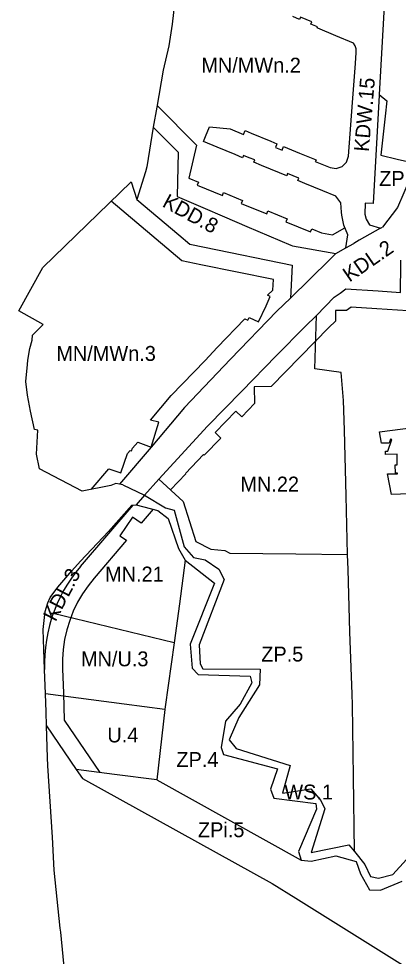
# Model space of a CAD drawing. Extents: x 7419601 to 7420547, y 5548907 to 5549873.
# Drawn here: x 7419651.8 to 7419779.2, y 5549211.8 to 5549526.6 of the extents above; entities that cross this region are included whole.
import ezdxf

# ---------------------------------------------------------------- set-up
doc = ezdxf.new("R2010")
doc.units = 0
for name, color, linetype in [('LIN_linie_rozgraniczajace', 7, 'Continuous'), ('LIN_nieprzekraczalna linia zabudowy', 7, 'Continuous'), ('TXT_opisy_przeznaczen', 7, 'Continuous')]:
    doc.layers.add(name, color=color, linetype=linetype)

msp = doc.modelspace()

# ---------------------------------------------------------------- linework, layer by layer
at = {"layer": 'LIN_linie_rozgraniczajace'}
for p, q in [((7419773.28, 5549456.31), (7419766.1, 5549452.22)), ((7419766.1, 5549452.22), (7419764.28, 5549451.17)), ((7419761.67, 5549449.69), (7419764.28, 5549451.17)), ((7419742.99, 5549432.82), (7419756.11, 5549445.62)), ((7419686.77, 5549370.13), (7419694.08, 5549366.64)), ((7419698.87, 5549371.96), (7419694.08, 5549366.64)), ((7419694.08, 5549366.64), (7419691.23, 5549363.38)), ((7419672.54, 5549342.67), (7419690.24, 5549363.28)), ((7419703.96, 5549317.03), (7419663.4, 5549326.89)), ((7419698.21, 5549271.06), (7419746.57, 5549244.06))]:
    msp.add_line(p, q, dxfattribs=at)
for points in [[(7419777.91, 5549592.55), (7419774.39, 5549528.85), (7419772.86, 5549501.2), (7419772.85, 5549500.98)], [(7419707.9, 5549572.09), (7419706.24, 5549550.17), (7419705.93, 5549547.4), (7419703.37, 5549524.79), (7419702.15, 5549517.49), (7419700.32, 5549509.31), (7419698.15, 5549496.9), (7419696.97, 5549490.2)], [(7419761.67, 5549449.69), (7419762.32, 5549454.07), (7419760.99, 5549457.25), (7419760.64, 5549458.99), (7419760.29, 5549460.68), (7419760.22, 5549461.67), (7419759.98, 5549464.76), (7419758.29, 5549467.03), (7419753.93, 5549468.82), (7419750.91, 5549470.07), (7419747.88, 5549471.32), (7419745.53, 5549472.29), (7419745.86, 5549473.07), (7419743.91, 5549473.87), (7419742.09, 5549474.62), (7419741.78, 5549473.84), (7419739.3, 5549474.86), (7419736.29, 5549476.1), (7419733.26, 5549477.34), (7419730.74, 5549478.38), (7419731.06, 5549479.17), (7419729.19, 5549479.94), (7419727.31, 5549480.71), (7419726.98, 5549479.93), (7419724.5, 5549480.97), (7419721.49, 5549482.23), (7419718.45, 5549483.48), (7419713.85, 5549485.36), (7419714.54, 5549487.03), (7419715.88, 5549490.27), (7419722.8, 5549489.61), (7419727.25, 5549487.77), (7419727.77, 5549489.02), (7419729.89, 5549488.14), (7419736.42, 5549485.45), (7419738.48, 5549484.6), (7419737.97, 5549483.36), (7419739.08, 5549482.89), (7419740.19, 5549482.44), (7419740.7, 5549483.69), (7419746.1, 5549481.46), (7419749.37, 5549480.12), (7419751.62, 5549479.19), (7419751.38, 5549478.64), (7419756.31, 5549476.61), (7419758.38, 5549476.28), (7419760.39, 5549476.93), (7419761.87, 5549478.42), (7419762.5, 5549480.43), (7419763.87, 5549498.44), (7419764.85, 5549511.52), (7419765.12, 5549515.25), (7419765.06, 5549516.49), (7419764.75, 5549517.47), (7419764.24, 5549518.36), (7419758.29, 5549520.87), (7419752.26, 5549523.43), (7419752.02, 5549523.54), (7419752.15, 5549523.87), (7419749.89, 5549524.8), (7419750.2, 5549525.59), (7419748.34, 5549526.35), (7419746.44, 5549527.14), (7419746.11, 5549526.35), (7419743.85, 5549527.29)], [(7419772.85, 5549500.98), (7419770.83, 5549464.52), (7419768.15, 5549464.7), (7419768.03, 5549461.02), (7419768.4, 5549459.24), (7419769.53, 5549457.42), (7419773.28, 5549456.31), (7419773.89, 5549456.66)], [(7419772.86, 5549501.2), (7419775.41, 5549499), (7419774.83, 5549493.83), (7419773.35, 5549480.78), (7419778.88, 5549479.48), (7419785.33, 5549477.97)], [(7419696.97, 5549490.2), (7419694.84, 5549476.85), (7419694.33, 5549475.22)], [(7419696.97, 5549490.2), (7419705.37, 5549481.74), (7419705.01, 5549466.93), (7419713.61, 5549463.23), (7419720.93, 5549460.09), (7419728.41, 5549456.87), (7419735.8, 5549453.71), (7419743.11, 5549450.55), (7419743.67, 5549450.31), (7419758.27, 5549447.73)], [(7419785.45, 5549478.26), (7419785.33, 5549477.97), (7419779.01, 5549463.24), (7419773.89, 5549456.66)], [(7419694.33, 5549475.22), (7419691.42, 5549465.86)], [(7419686.77, 5549370.13), (7419685.59, 5549370.35), (7419684.41, 5549370.57), (7419682.74, 5549369.89), (7419673.14, 5549367.93), (7419658.79, 5549375.45), (7419657.77, 5549380.42), (7419658.24, 5549388.47), (7419657.12, 5549388.69), (7419655.81, 5549394.88), (7419654.71, 5549400.19), (7419654.17, 5549404.81), (7419654.71, 5549410.47), (7419654.85, 5549411.95), (7419655.5, 5549415.92), (7419656.29, 5549418.71), (7419656.41, 5549420.32), (7419660.01, 5549423.96), (7419651.81, 5549428.47), (7419659.89, 5549443.1), (7419689.55, 5549471.82), (7419691.42, 5549465.86)], [(7419691.42, 5549465.86), (7419698.5, 5549459.94), (7419705.59, 5549454.01), (7419709.25, 5549450.87), (7419714.16, 5549449.88), (7419743.61, 5549443.9), (7419742.99, 5549432.82)], [(7419756.11, 5549445.62), (7419758.27, 5549447.73), (7419758.31, 5549447.77), (7419761.67, 5549449.69)], [(7419751.74, 5549427), (7419757.74, 5549433.05), (7419759.68, 5549434.46), (7419761.59, 5549435.87), (7419772.43, 5549435.18), (7419779.99, 5549434.69), (7419780.12, 5549444.2), (7419780.14, 5549445.53)], [(7419742.99, 5549432.82), (7419738.43, 5549428.39), (7419722.95, 5549412.24), (7419707.46, 5549396.1), (7419696.31, 5549382.76), (7419685.59, 5549370.35)], [(7419751.74, 5549427), (7419747.99, 5549423.22), (7419738.24, 5549413.4), (7419726.7, 5549401.57), (7419715.17, 5549389.75), (7419698.87, 5549371.96)], [(7419762.23, 5549346.67), (7419761.71, 5549366.37), (7419761.12, 5549388.42), (7419760.86, 5549398.45), (7419760.08, 5549407.83), (7419751.2, 5549408.99), (7419751.74, 5549427)], [(7419698.87, 5549371.96), (7419706.96, 5549364.5), (7419711.27, 5549351.1), (7419716.32, 5549348.47), (7419720.98, 5549348.02), (7419722.66, 5549347.17), (7419744.84, 5549346.89), (7419762.23, 5549346.67)], [(7419694.08, 5549366.64), (7419701.12, 5549362.38), (7419704.03, 5549361.57), (7419707.33, 5549349.23), (7419710.51, 5549345.74), (7419714.4, 5549344.92), (7419719.02, 5549341.8), (7419720.82, 5549338.28), (7419712.42, 5549316.32), (7419712.72, 5549310.01), (7419713.64, 5549308.26), (7419732.89, 5549308.23), (7419732.62, 5549302.94), (7419725.69, 5549292.02), (7419722.45, 5549284.49), (7419724.81, 5549281.56), (7419742.94, 5549275.84), (7419740.33, 5549266.59), (7419749.87, 5549267.98), (7419753.2, 5549264.14), (7419754.55, 5549261.27), (7419749.99, 5549246.63), (7419762.65, 5549249.26), (7419764.51, 5549246.94)], [(7419660.84, 5549299.92), (7419660.51, 5549308.1), (7419659.98, 5549321.47), (7419660.69, 5549327.55), (7419661.62, 5549330.48), (7419662.39, 5549332.24), (7419664.89, 5549335.74), (7419669.61, 5549341.18), (7419672.51, 5549344.47), (7419681.9, 5549354.46), (7419689.78, 5549363.23), (7419690.24, 5549363.28), (7419691.23, 5549363.38)], [(7419691.23, 5549363.38), (7419698.55, 5549361.52), (7419702.02, 5549358.75), (7419705.41, 5549348.71), (7419707.66, 5549344.84)], [(7419707.66, 5549344.84), (7419705.78, 5549330.1), (7419703.96, 5549317.03), (7419701, 5549295.54), (7419700.88, 5549294.65)], [(7419707.66, 5549344.84), (7419717.51, 5549337.05), (7419709.37, 5549316.61), (7419709.99, 5549308.52), (7419712.02, 5549306.36), (7419729.47, 5549305.82), (7419730.07, 5549303.6), (7419726.12, 5549296.43), (7419721.2, 5549290.75), (7419719.76, 5549281.9), (7419720.6, 5549279.55), (7419738.65, 5549274.74), (7419736.38, 5549267.93), (7419737.49, 5549264.9), (7419751.53, 5549263.1), (7419751.8, 5549261.19), (7419745.75, 5549246.95), (7419746.57, 5549244.06), (7419749.97, 5549243.76), (7419758.31, 5549245.52), (7419765.1, 5549243.62), (7419766.54, 5549239.49), (7419769.52, 5549234.07), (7419773.26, 5549233.97), (7419780.51, 5549236.96)], [(7419764.51, 5549246.94), (7419764.16, 5549272.03), (7419763.82, 5549296.21), (7419763.76, 5549299.76), (7419763.01, 5549320.75), (7419762.36, 5549341.64), (7419762.23, 5549346.67)], [(7419672.54, 5549342.67), (7419670.99, 5549340.78), (7419669.53, 5549338.79), (7419668.15, 5549336.72), (7419666.87, 5549334.56), (7419665.7, 5549332.34), (7419664.63, 5549330.06), (7419663.68, 5549327.72), (7419663.4, 5549326.89), (7419662.85, 5549325.33), (7419662.14, 5549322.9), (7419661.56, 5549320.45), (7419661.1, 5549317.98), (7419660.77, 5549315.5), (7419660.56, 5549313.02), (7419660.48, 5549310.55), (7419660.51, 5549308.1)], [(7419700.88, 5549294.65), (7419687.16, 5549296.46), (7419660.84, 5549299.92)], [(7419661.45, 5549278.55), (7419661.15, 5549289.17), (7419661.01, 5549293.92), (7419660.84, 5549299.92)], [(7419700.88, 5549294.65), (7419698.21, 5549271.06), (7419683.97, 5549272.88), (7419671.11, 5549274.52)], [(7419661.15, 5549289.17), (7419671.11, 5549274.52), (7419673.17, 5549271.49), (7419736.84, 5549236.24), (7419744.84, 5549231.32), (7419790.54, 5549202.77)], [(7419665.75, 5549221.29), (7419663.69, 5549240.66), (7419663.11, 5549251.78), (7419661.53, 5549275.74), (7419661.45, 5549278.55)], [(7419764.51, 5549246.94), (7419767.98, 5549242.63), (7419769.9, 5549238.6), (7419772.6, 5549237.98), (7419777.35, 5549239.25), (7419795.85, 5549259.49), (7419799.55, 5549262.49)], [(7419667.53, 5549203.52), (7419665.9, 5549219.93), (7419665.75, 5549221.29)]]:
    msp.add_lwpolyline(points, dxfattribs=at)
at = {"layer": 'LIN_nieprzekraczalna linia zabudowy'}
for p, q in [((7419676.09, 5549368.53), (7419682.05, 5549375.43)), ((7419696.98, 5549361.92), (7419692.96, 5549357.23)), ((7419688, 5549351.46), (7419677.1, 5549338.76)), ((7419666.51, 5549308.34), (7419666.84, 5549300.12))]:
    msp.add_line(p, q, dxfattribs=at)
for points in [[(7419698.24, 5549497.43), (7419711.43, 5549484.15), (7419708.86, 5549473.07), (7419712.14, 5549471.72), (7419711.72, 5549470.7), (7419720.18, 5549467.21), (7419720.6, 5549468.22), (7419726.94, 5549465.61), (7419726.52, 5549464.59), (7419735.05, 5549461.07), (7419735.47, 5549462.09), (7419741.9, 5549459.44), (7419741.48, 5549458.42), (7419749.79, 5549455), (7419750.21, 5549456.01), (7419753.5, 5549454.65), (7419757.16, 5549454.02)], [(7419737.13, 5549435.49), (7419737.33, 5549439.05), (7419712.97, 5549444), (7419706.56, 5549445.29), (7419682.79, 5549465.28)], [(7419757.16, 5549454.02), (7419761.34, 5549456.41)], [(7419727.67, 5549425.83), (7419728.69, 5549425.35), (7419729.12, 5549426.26), (7419732.28, 5549424.77), (7419734.83, 5549430.22), (7419736.27, 5549433.3), (7419735.34, 5549433.75)], [(7419735.34, 5549433.75), (7419737.13, 5549435.49)], [(7419786, 5549435.19), (7419785.9, 5549428.29), (7419772.05, 5549429.19), (7419763.39, 5549429.74), (7419761.85, 5549428.59), (7419758.12, 5549428.58), (7419758.11, 5549425.04), (7419755.91, 5549422.92)], [(7419756.05, 5549423.06), (7419736.56, 5549403.09), (7419730.89, 5549402.97), (7419731, 5549397.4), (7419726.67, 5549392.96), (7419724.65, 5549394.88), (7419717.72, 5549387.62), (7419719.66, 5549385.77), (7419714.08, 5549380.06), (7419713.82, 5549380.31), (7419707.76, 5549373.87), (7419707.91, 5549373.73), (7419702.71, 5549368.41)], [(7419718.41, 5549416.18), (7419727.67, 5549425.83)], [(7419696.06, 5549391.82), (7419702.99, 5549400.11), (7419714.37, 5549411.88), (7419718.41, 5549416.18)], [(7419682.05, 5549375.43), (7419686.06, 5549374.11), (7419688.33, 5549380.66), (7419689.26, 5549381.66), (7419689.68, 5549381.52), (7419689.99, 5549382.45), (7419691.79, 5549384.4), (7419696.31, 5549382.76), (7419698.79, 5549391.08), (7419696.06, 5549391.82)], [(7419783.04, 5549367.12), (7419776.97, 5549366.9), (7419775.64, 5549373.76), (7419778.92, 5549373.8), (7419778.92, 5549374.02), (7419778.26, 5549374.01), (7419778.22, 5549376.85), (7419778.88, 5549376.86), (7419778.83, 5549380.38), (7419774.93, 5549380.33), (7419774.92, 5549381.4), (7419775.73, 5549381.41), (7419777.07, 5549385.31), (7419776.64, 5549385.45), (7419776.18, 5549384.12), (7419773.64, 5549384.09), (7419772.9, 5549387.91), (7419784.28, 5549389.31), (7419791.8, 5549387.83), (7419814.1, 5549383.39)], [(7419692.96, 5549357.23), (7419690, 5549359.24), (7419685.75, 5549352.99), (7419688, 5549351.46)], [(7419677.1, 5549338.76), (7419675.08, 5549336.23), (7419673.23, 5549333.52), (7419671.57, 5549330.66), (7419670.13, 5549327.66), (7419668.92, 5549324.56), (7419667.94, 5549321.37), (7419667.21, 5549318.12), (7419666.73, 5549314.85), (7419666.5, 5549311.58), (7419666.51, 5549308.34)], [(7419666.84, 5549300.12), (7419667.09, 5549291.1)], [(7419667.09, 5549291.1), (7419679.05, 5549273.51)]]:
    msp.add_lwpolyline(points, dxfattribs=at)

# ---------------------------------------------------------------- texts
at = {"layer": 'TXT_opisy_przeznaczen'}
for s, p in [('MN/MWn.2', (7419713.09, 5549508.5)), ('ZP.1', (7419772.81, 5549470.47)), ('MN/MWn.3', (7419664.41, 5549411.71)), ('MN.22', (7419726.21, 5549367.84)), ('MN.21', (7419680.79, 5549337.63)), ('MN/U.3', (7419672.69, 5549309.16)), ('ZP.5', (7419733.22, 5549310.77)), ('U.4', (7419681.56, 5549283.61)), ('ZP.4', (7419704.73, 5549275.36)), ('WS.1', (7419740.97, 5549264.44)), ('ZPi.5', (7419711.96, 5549251.78))]:
    msp.add_text(s, height=5, dxfattribs=at).set_placement(p)
for s, rotation, p in [('KDW.15', 85.1932, (7419769.33, 5549481.79)), ('KDD.8', 331.5257, (7419699.67, 5549463.67)), ('KDL.2', 34.6762, (7419762.82, 5549437.97)), ('KDL.3', 62.4023, (7419664.14, 5549323.88))]:
    msp.add_text(s, height=5, rotation=rotation, dxfattribs=at).set_placement(p)

doc.saveas('drawing.dxf')
